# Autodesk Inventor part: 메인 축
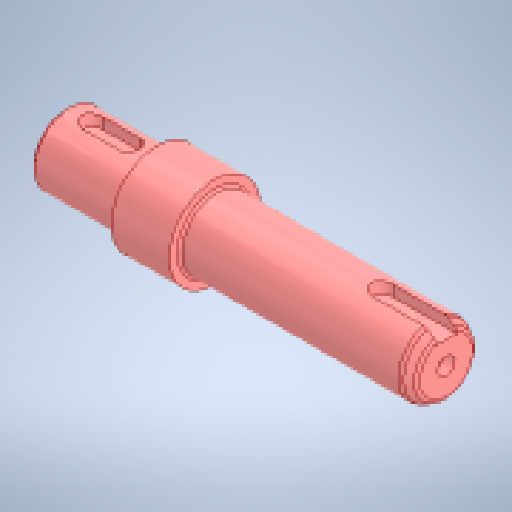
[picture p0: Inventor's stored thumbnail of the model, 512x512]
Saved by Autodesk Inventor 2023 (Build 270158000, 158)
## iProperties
Created: 2025-04
Part Number: 메인 축
Material: 강철, 탄소
Document SubType Name: Modeling
Designer: user
Density: 7.85 g/cm^3
Appearance: 기본값
Author: jhkim
Sending System: Autodesk Inventor 2026
Preprocessor: ST-DEVELOPER v20.1
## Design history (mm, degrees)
feature "솔리드1"
node "솔리드2"
